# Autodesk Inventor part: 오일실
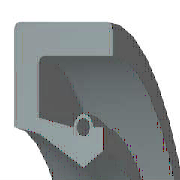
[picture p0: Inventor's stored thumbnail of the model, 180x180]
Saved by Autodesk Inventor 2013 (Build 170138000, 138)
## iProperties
IsCustomPart: 1
Company: 한국ATC센터
Created: 2014-11
Part Number: 오일실
Material: Rubber
Description: 오일-실
Document SubType Name: Modeling
Standard: KS B 2804
Designer: KYOUNG IL JANG
Standards Organization: KS
Language: ko-KR
Size Designation: S - 25 40 8
Categories: <MemberInstance><Categories><Category DisplayName="샤프트 부품" InternalName="7f7aeb1f-a693-4053-b835-cee3144e0d98" Mnemonic="SHFT"><Category DisplayName="실링" Intern
Density: 0.93 g/cm^3
Mass: 2.48215 g
Surface Area: 40.3381 cm^2
Volume: 2.66898 cm^3
Author: KYOUNG IL JANG
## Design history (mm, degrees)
revolve "본체" stored, may be unused: angle "d17" = 90 deg
revolve "스프링1" stored, may be unused: angle "d18" = 90 deg
body "Solid1"
sketch "스케치1"
  geometry: L1 (0, 20)-(8, 20); L2 (8, 20)-(8, 18.75); L3 (8, 18.75)-(1.75, 18.75); L4 (0, 20)-(0, 14.6); L5 (0, 14.6)-(1.75, 14.25); L6 (1.75, 14.25)-(4.9, 12.5); L7 (4.9, 12.5)-(0, 12.5); L8 (6.3, 13.375)-(6.3, 14.6); L9 (0, 0)-(9.586, 0) reference; L10 (4.9, 12.5)-(6.3, 13.375); L11 (0, 18)-(0, -3) reference; L12 (-1.917, 0)-(11.503, 0) reference; L13 (4.2, 14.6)-(1.75, 15.09); L14 (1.75, 15.09)-(1.75, 18.75); L15 (6.3, 14.6)-(5.6, 14.6); C1 r 0.455 at (4.9, 14.6); A1 r 0.7 centre (4.9, 14.6) between (5.6, 14.6) and (4.2, 14.6)
  constraints: 26 end point, 5 horizontal alignment, 4 perpendicular, 2 centre point, 2 collinear, 2 horizontal, 2 parallel, 2 point on circle, 2 point on line, 2 vertical alignment, 1 coincident
  dimensions: "d0" = 40 diameter of L1 L9 (= SD2); "d1" = 26.75 diameter of L8.start L9 (= ABDM); "d2" = 1.25 distance of L1.end L2.end (computed from SD); "d3" = 0.91 diameter of C1 (= SPDI); "d4" = 1.4 diameter of A1 (= SPDA); "d5" = 25 diameter of L6.end L9 (= NND); "d6" = 28.5 diameter of L5.end L9 (= TKDM); "d7" = 29.2 diameter of L4.end L9 (= HLDM); "d8" = 4.9 distance from line of C1.centre L4 (= SPDST); "d9" = 6.3 distance between parallel lines of L8 L4 (= SDI); "d10" = 8 distance between parallel lines of L2 L4 (= SWDT); "d12" = 1.75 distance between parallel lines of L14 L4 (= SD)
fillet "모깎기1" dims "d11" = 0.3 (= RR)
other parameters: "SD2" = 40 [user parameter; used in 1 equation term], "SWDT" = 8 [user parameter; used in 1 equation term], "RR" = 0.3 [user parameter; used in 1 equation term], "SD" = 1.75 [user parameter; used in 2 equation terms], "NND" = 25 [user parameter; used in 1 equation term], "SPDA" = 1.4 [user parameter; used in 1 equation term], "SPDI" = 0.91 [user parameter; used in 1 equation term], "TKDM" = 28.5 [user parameter; used in 1 equation term], "HLDM" = 29.2 [user parameter; used in 1 equation term], "ABDM" = 26.75 [user parameter; used in 1 equation term], "SDI" = 6.3 [user parameter; used in 1 equation term], "SPDST" = 4.9 [user parameter; used in 1 equation term], "d13" = 0, "d14" = 0, "d15" = 0, "LAB" = 0.35 [user parameter]
